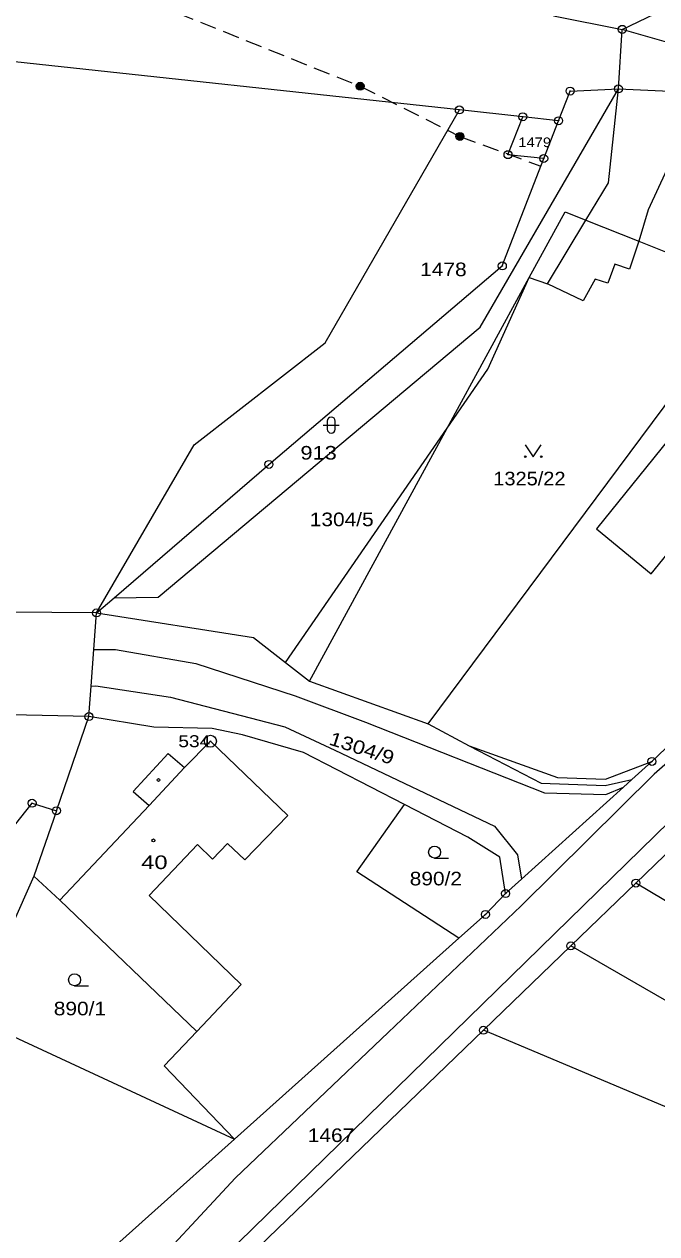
# Model space of a CAD drawing. Extents: x -872229 to -869198, y -1075981 to -1074329.
# Drawn here: x -871207 to -871127.8, y -1075369.5 to -1075218 of the extents above; entities that cross this region are included whole.
import ezdxf
from ezdxf.enums import TextEntityAlignment as Align

# ---------------------------------------------------------------- set-up
doc = ezdxf.new("R2010")
doc.units = 0
doc.header["$LTSCALE"] = 0.68
doc.linetypes.add('MEDIUM_DASHED', pattern=[4.5, 3, -1.5])
for name, color, linetype, lineweight in [('1', 7, 'Continuous', 25), ('3', 7, 'Continuous', 25), ('4', 7, 'Continuous', 13), ('5', 7, 'Continuous', 25), ('6', 7, 'Continuous', 25), ('8', 7, 'Continuous', 25)]:
    doc.layers.add(name, color=color, linetype=linetype, lineweight=lineweight)
doc.layers.add('2', color=7, linetype='Continuous')

msp = doc.modelspace()

# ---------------------------------------------------------------- linework, layer by layer
at = {"layer": '1'}
for p, q in [((-871144.59, -1075229.61), (-871152.53, -1075228.75)), ((-871197.94, -1075291.72), (-871195.74, -1075289.82)), ((-871156.43, -1075305.59), (-871151.31, -1075308.38)), ((-871113.42, -1075309.13), (-871130.43, -1075325.54)), ((-871202.96, -1075316.49), (-871205.8, -1075324.68)), ((-871130.43, -1075325.54), (-871138.58, -1075333.41)), ((-871149.52, -1075343.97), (-871178.79, -1075372.22)), ((-871078.37, -1075373.89), (-871149.52, -1075343.97))]:
    msp.add_line(p, q, dxfattribs=at)
for points in [[(-871152.53, -1075228.75), (-871324.15, -1075210.15), (-871498.95, -1075191.88), (-871564.6, -1075180.17), (-871590.36, -1075167.06), (-871608.79, -1075266.42)], [(-871140.73, -1075216.95), (-871132.14, -1075218.66), (-871123.91, -1075214.69)], [(-871140.11, -1075230.1), (-871138.66, -1075226.39), (-871132.62, -1075226.11), (-871132.14, -1075218.66)], [(-871093.1, -1075221.48), (-871116.67, -1075223.11), (-871132.14, -1075218.66)], [(-871195.74, -1075289.82), (-871190.23, -1075289.74), (-871149.91, -1075255.96), (-871132.62, -1075226.11)], [(-871141.5, -1075250.52), (-871136.68, -1075242.53), (-871133.87, -1075237.87), (-871132.62, -1075226.11)], [(-871132.62, -1075226.11), (-871114.29, -1075226.93), (-871095.65, -1075227.79), (-871094.24, -1075242.63), (-871087.01, -1075243.79), (-871083.47, -1075253.75), (-871081.37, -1075254)], [(-871197.94, -1075291.72), (-871185.72, -1075270.67), (-871169.32, -1075257.9), (-871152.53, -1075228.75)], [(-871141.97, -1075234.83), (-871146.44, -1075234.35), (-871144.59, -1075229.61)], [(-871141.97, -1075234.83), (-871140.11, -1075230.1), (-871144.59, -1075229.61)], [(-871195.74, -1075289.82), (-871176.36, -1075273.13), (-871147.15, -1075248.28), (-871142.34, -1075235.78), (-871141.97, -1075234.83)], [(-871114.29, -1075249), (-871111.33, -1075241.33), (-871122.72, -1075243.71), (-871120.98, -1075237.29), (-871126.58, -1075236.21), (-871128.88, -1075241.26), (-871130.08, -1075245.17), (-871131.22, -1075248.69), (-871133.07, -1075248.06), (-871133.96, -1075250.43), (-871135.52, -1075249.95), (-871137.04, -1075252.66), (-871141.5, -1075250.52)], [(-871174.28, -1075297.93), (-871154.05, -1075268.6), (-871148.96, -1075261.22), (-871143.79, -1075249.74), (-871141.5, -1075250.52)], [(-871156.43, -1075305.59), (-871115.7, -1075250.9), (-871114.29, -1075249)], [(-871197.94, -1075291.72), (-871226.01, -1075291.51), (-871257.41, -1075294.08), (-871286.96, -1075298.91), (-871317.28, -1075305.51), (-871377.38, -1075316.93)], [(-871198.89, -1075304.69), (-871198.62, -1075300.91), (-871198.28, -1075296.29), (-871197.94, -1075291.72)], [(-871197.94, -1075291.72), (-871178.28, -1075294.81), (-871174.28, -1075297.93)], [(-871174.28, -1075297.93), (-871171.28, -1075300.27), (-871156.43, -1075305.59)], [(-871119.87, -1075302.18), (-871128.42, -1075310.32), (-871130.92, -1075312.57)], [(-871198.89, -1075304.69), (-871226.19, -1075304.09), (-871258.51, -1075307.55), (-871284.79, -1075311.01), (-871308.94, -1075316.35)], [(-871243.8, -1075363.33), (-871206.01, -1075315.54), (-871202.96, -1075316.49), (-871198.89, -1075304.69)], [(-871159.38, -1075315.72), (-871172.04, -1075309.18), (-871179.69, -1075306.97), (-871183.47, -1075306.17), (-871190.75, -1075306.03), (-871198.89, -1075304.69)], [(-871151.31, -1075308.38), (-871142.29, -1075313.05), (-871134.29, -1075313.31), (-871130.92, -1075312.57)], [(-871130.92, -1075312.57), (-871131.97, -1075313.52), (-871144.74, -1075325.04), (-871146.74, -1075326.85)], [(-871152.59, -1075332.45), (-871165.34, -1075324.15), (-871159.38, -1075315.72)], [(-871146.74, -1075326.85), (-871147.48, -1075322.31), (-871151.47, -1075319.8), (-871159.38, -1075315.72)], [(-871205.8, -1075324.68), (-871208.57, -1075330.98), (-871218.91, -1075339.87), (-871180.67, -1075357.59)], [(-871205.8, -1075324.68), (-871202.55, -1075327.7), (-871185.37, -1075344.12), (-871189.49, -1075348.43), (-871180.67, -1075357.59)], [(-871074.84, -1075352.78), (-871079.33, -1075352.72), (-871094.35, -1075347.04), (-871130.43, -1075325.54)], [(-871146.74, -1075326.85), (-871149.26, -1075329.47), (-871152.59, -1075332.45), (-871180.67, -1075357.59), (-871200.62, -1075375.46)], [(-871077.5, -1075368.64), (-871138.58, -1075333.41), (-871149.52, -1075343.97)]]:
    msp.add_lwpolyline(points, dxfattribs=at)
msp.add_lwpolyline([(-871114.73, -1075255.63), (-871135.35, -1075281.2), (-871128.52, -1075286.81), (-871107.81, -1075261.35), (-871112.73, -1075257.25)], close=True, dxfattribs=at)
at = {"layer": '3'}
for p, q in [((-871169.571, -1075268.211), (-871167.569, -1075268.211)), ((-871169.071, -1075267.711), (-871169.071, -1075268.712)), ((-871168.069, -1075268.712), (-871168.069, -1075267.711)), ((-871155.623, -1075322.42), (-871153.873, -1075322.42)), ((-871200.693, -1075338.4), (-871198.943, -1075338.4))]:
    msp.add_line(p, q, dxfattribs=at)
msp.add_lwpolyline([(-871144.28, -1075270.669), (-871143.28, -1075272.17), (-871142.28, -1075270.669)], dxfattribs=at)
for centre, radius in [((-871144.28, -1075272.1695), 0.1), ((-871142.28, -1075272.1695), 0.1), ((-871155.6229, -1075321.6698), 0.75), ((-871200.6929, -1075337.6498), 0.75)]:
    msp.add_circle(centre, radius, dxfattribs=at)
for centre, start, end in [((-871168.57, -1075267.7109), 0, 180), ((-871168.57, -1075268.7109), 180, 359.98789)]:
    msp.add_arc(centre, 0.5, start, end, dxfattribs=at)
at = {"layer": '4'}
for p, q in [((-871143.79, -1075249.74), (-871139.3, -1075241.49)), ((-871130.08, -1075245.17), (-871115.7, -1075250.9)), ((-871154.05, -1075268.6), (-871143.79, -1075249.74)), ((-871171.28, -1075300.27), (-871154.05, -1075268.6)), ((-871198.28, -1075296.29), (-871195.57, -1075296.31)), ((-871195.57, -1075296.31), (-871185.5, -1075298.06)), ((-871185.5, -1075298.06), (-871173.09, -1075302.09)), ((-871198.62, -1075300.91), (-871198.04, -1075300.83)), ((-871198.04, -1075300.83), (-871188.7, -1075302.25)), ((-871188.7, -1075302.25), (-871174.37, -1075306)), ((-871173.09, -1075302.09), (-871164.26, -1075305.38)), ((-871118.65, -1075303.5), (-871128.14, -1075311.92)), ((-871174.37, -1075306), (-871168.13, -1075308.89)), ((-871164.26, -1075305.38), (-871141.89, -1075314.23)), ((-871186.94, -1075311.08), (-871183.69, -1075307.78)), ((-871183.69, -1075307.78), (-871174, -1075317.1)), ((-871168.13, -1075308.89), (-871148.13, -1075318.4)), ((-871151.31, -1075308.38), (-871140.23, -1075312.34)), ((-871193.35, -1075314.06), (-871188.96, -1075309.34)), ((-871188.96, -1075309.34), (-871186.94, -1075311.08)), ((-871180.16, -1075370.54), (-871118.25, -1075310.04)), ((-871134.25, -1075312.54), (-871128.42, -1075310.32)), ((-871191.36, -1075315.85), (-871186.94, -1075311.08)), ((-871128.14, -1075311.92), (-871144.78, -1075328.38)), ((-871140.23, -1075312.34), (-871134.25, -1075312.54)), ((-871134.21, -1075314.46), (-871131.97, -1075313.52)), ((-871193.35, -1075314.06), (-871191.36, -1075315.85)), ((-871141.89, -1075314.23), (-871134.21, -1075314.46)), ((-871202.55, -1075327.7), (-871191.36, -1075315.85)), ((-871191.36, -1075327.09), (-871185.32, -1075320.73)), ((-871185.32, -1075320.73), (-871183.41, -1075322.55)), ((-871191.36, -1075327.09), (-871179.85, -1075338.26)), ((-871185.37, -1075344.12), (-871179.85, -1075338.26))]:
    msp.add_line(p, q, dxfattribs=at)
for points in [[(-871139.3, -1075241.49), (-871136.68, -1075242.53), (-871130.08, -1075245.17)], [(-871183.41, -1075322.55), (-871181.54, -1075320.58), (-871179.36, -1075322.65), (-871174, -1075317.1)], [(-871148.13, -1075318.4), (-871145.25, -1075321.99), (-871144.74, -1075325.04)], [(-871144.78, -1075328.38), (-871161.44, -1075344.27), (-871180.53, -1075362.44), (-871193.17, -1075376.03)]]:
    msp.add_lwpolyline(points, dxfattribs=at)
at = {"layer": '5'}
for centre in [(-871190.1768, -1075312.6392), (-871190.8268, -1075320.1992)]:
    msp.add_circle(centre, 0.175, dxfattribs=at)
at = {"layer": '6', "linetype": 'MEDIUM_DASHED'}
for p, q in [((-871219.01, -1075204.11), (-871164.94, -1075225.78)), ((-871164.94, -1075225.78), (-871152.45, -1075232.06)), ((-871152.45, -1075232.06), (-871142.34, -1075235.78))]:
    msp.add_line(p, q, dxfattribs=at)
at = {"layer": '6'}
for centre, radius in [((-871164.9434, -1075225.7799), 0.5), ((-871164.9434, -1075225.7799), 0.4), ((-871164.9434, -1075225.7799), 0.3), ((-871164.9434, -1075225.7799), 0.2), ((-871164.9434, -1075225.7799), 0.1), ((-871152.4534, -1075232.0599), 0.5), ((-871152.4534, -1075232.0599), 0.4), ((-871152.4534, -1075232.0599), 0.3), ((-871152.4534, -1075232.0599), 0.2), ((-871152.4534, -1075232.0599), 0.1)]:
    msp.add_circle(centre, radius, dxfattribs=at)
at = {"layer": '8'}
for centre, radius in [((-871132.14, -1075218.6599), 0.5), ((-871132.14, -1075218.6599), 0.0303), ((-871138.66, -1075226.3899), 0.5), ((-871132.62, -1075226.1099), 0.5), ((-871138.66, -1075226.3899), 0.0303), ((-871132.62, -1075226.1099), 0.0303), ((-871152.53, -1075228.7499), 0.5), ((-871152.53, -1075228.7499), 0.0303), ((-871144.59, -1075229.6099), 0.5), ((-871144.59, -1075229.6099), 0.0303), ((-871140.11, -1075230.0999), 0.5), ((-871140.11, -1075230.0999), 0.0303), ((-871146.44, -1075234.3499), 0.5), ((-871146.44, -1075234.3499), 0.0303), ((-871141.97, -1075234.8299), 0.5), ((-871141.97, -1075234.8299), 0.0303), ((-871147.15, -1075248.2799), 0.5), ((-871147.15, -1075248.2799), 0.0303), ((-871176.36, -1075273.1299), 0.5), ((-871176.36, -1075273.1299), 0.0303), ((-871197.94, -1075291.7199), 0.5), ((-871197.94, -1075291.7199), 0.0303), ((-871198.89, -1075304.6899), 0.5), ((-871198.89, -1075304.6899), 0.0303), ((-871183.69, -1075307.7798), 0.75), ((-871183.69, -1075307.7798), 0.03), ((-871128.42, -1075310.3199), 0.5), ((-871128.42, -1075310.3199), 0.0303), ((-871206.01, -1075315.5399), 0.5), ((-871206.01, -1075315.5399), 0.0303), ((-871202.96, -1075316.4899), 0.5), ((-871202.96, -1075316.4899), 0.0303), ((-871130.43, -1075325.5399), 0.5), ((-871130.43, -1075325.5399), 0.0303), ((-871146.74, -1075326.8499), 0.5), ((-871146.74, -1075326.8499), 0.0303), ((-871149.26, -1075329.4699), 0.5), ((-871149.26, -1075329.4699), 0.0303), ((-871138.58, -1075333.4099), 0.5), ((-871138.58, -1075333.4099), 0.0303), ((-871149.52, -1075343.9699), 0.5), ((-871149.52, -1075343.9699), 0.0303)]:
    msp.add_circle(centre, radius, dxfattribs=at)

# ---------------------------------------------------------------- texts
at = {"layer": '2'}
for s, height, width, p in [('1479', 1.2, 1.15, (-871145.15, -1075233.4)), ('1478', 1.7, 1.15, (-871157.43, -1075249.56)), ('913', 1.7, 1.2, (-871172.42, -1075272.52)), ('1325/22', 1.7, 1.1, (-871148.28, -1075275.75)), ('1304/5', 1.7, 1.15, (-871171.25, -1075280.86)), ('40', 1.7, 1.3, (-871192.34, -1075323.79)), ('890/2', 1.7, 1.15, (-871158.74, -1075325.83)), ('890/1', 1.7, 1.15, (-871203.29, -1075342.1)), ('1467', 1.7, 1.15, (-871171.5, -1075357.96))]:
    msp.add_text(s, height=height, dxfattribs=dict(at, width=width)).set_placement(p)
at = {"layer": '2', "width": 1.2}
msp.add_text('1304/9', height=1.7, rotation=342, dxfattribs=at).set_placement((-871168.962, -1075308.168))
at = {"layer": '8', "width": 1.2}
msp.add_text('534', height=1.5, dxfattribs=at).set_placement((-871183.69, -1075308.53), align=Align.RIGHT)

doc.saveas('drawing.dxf')
